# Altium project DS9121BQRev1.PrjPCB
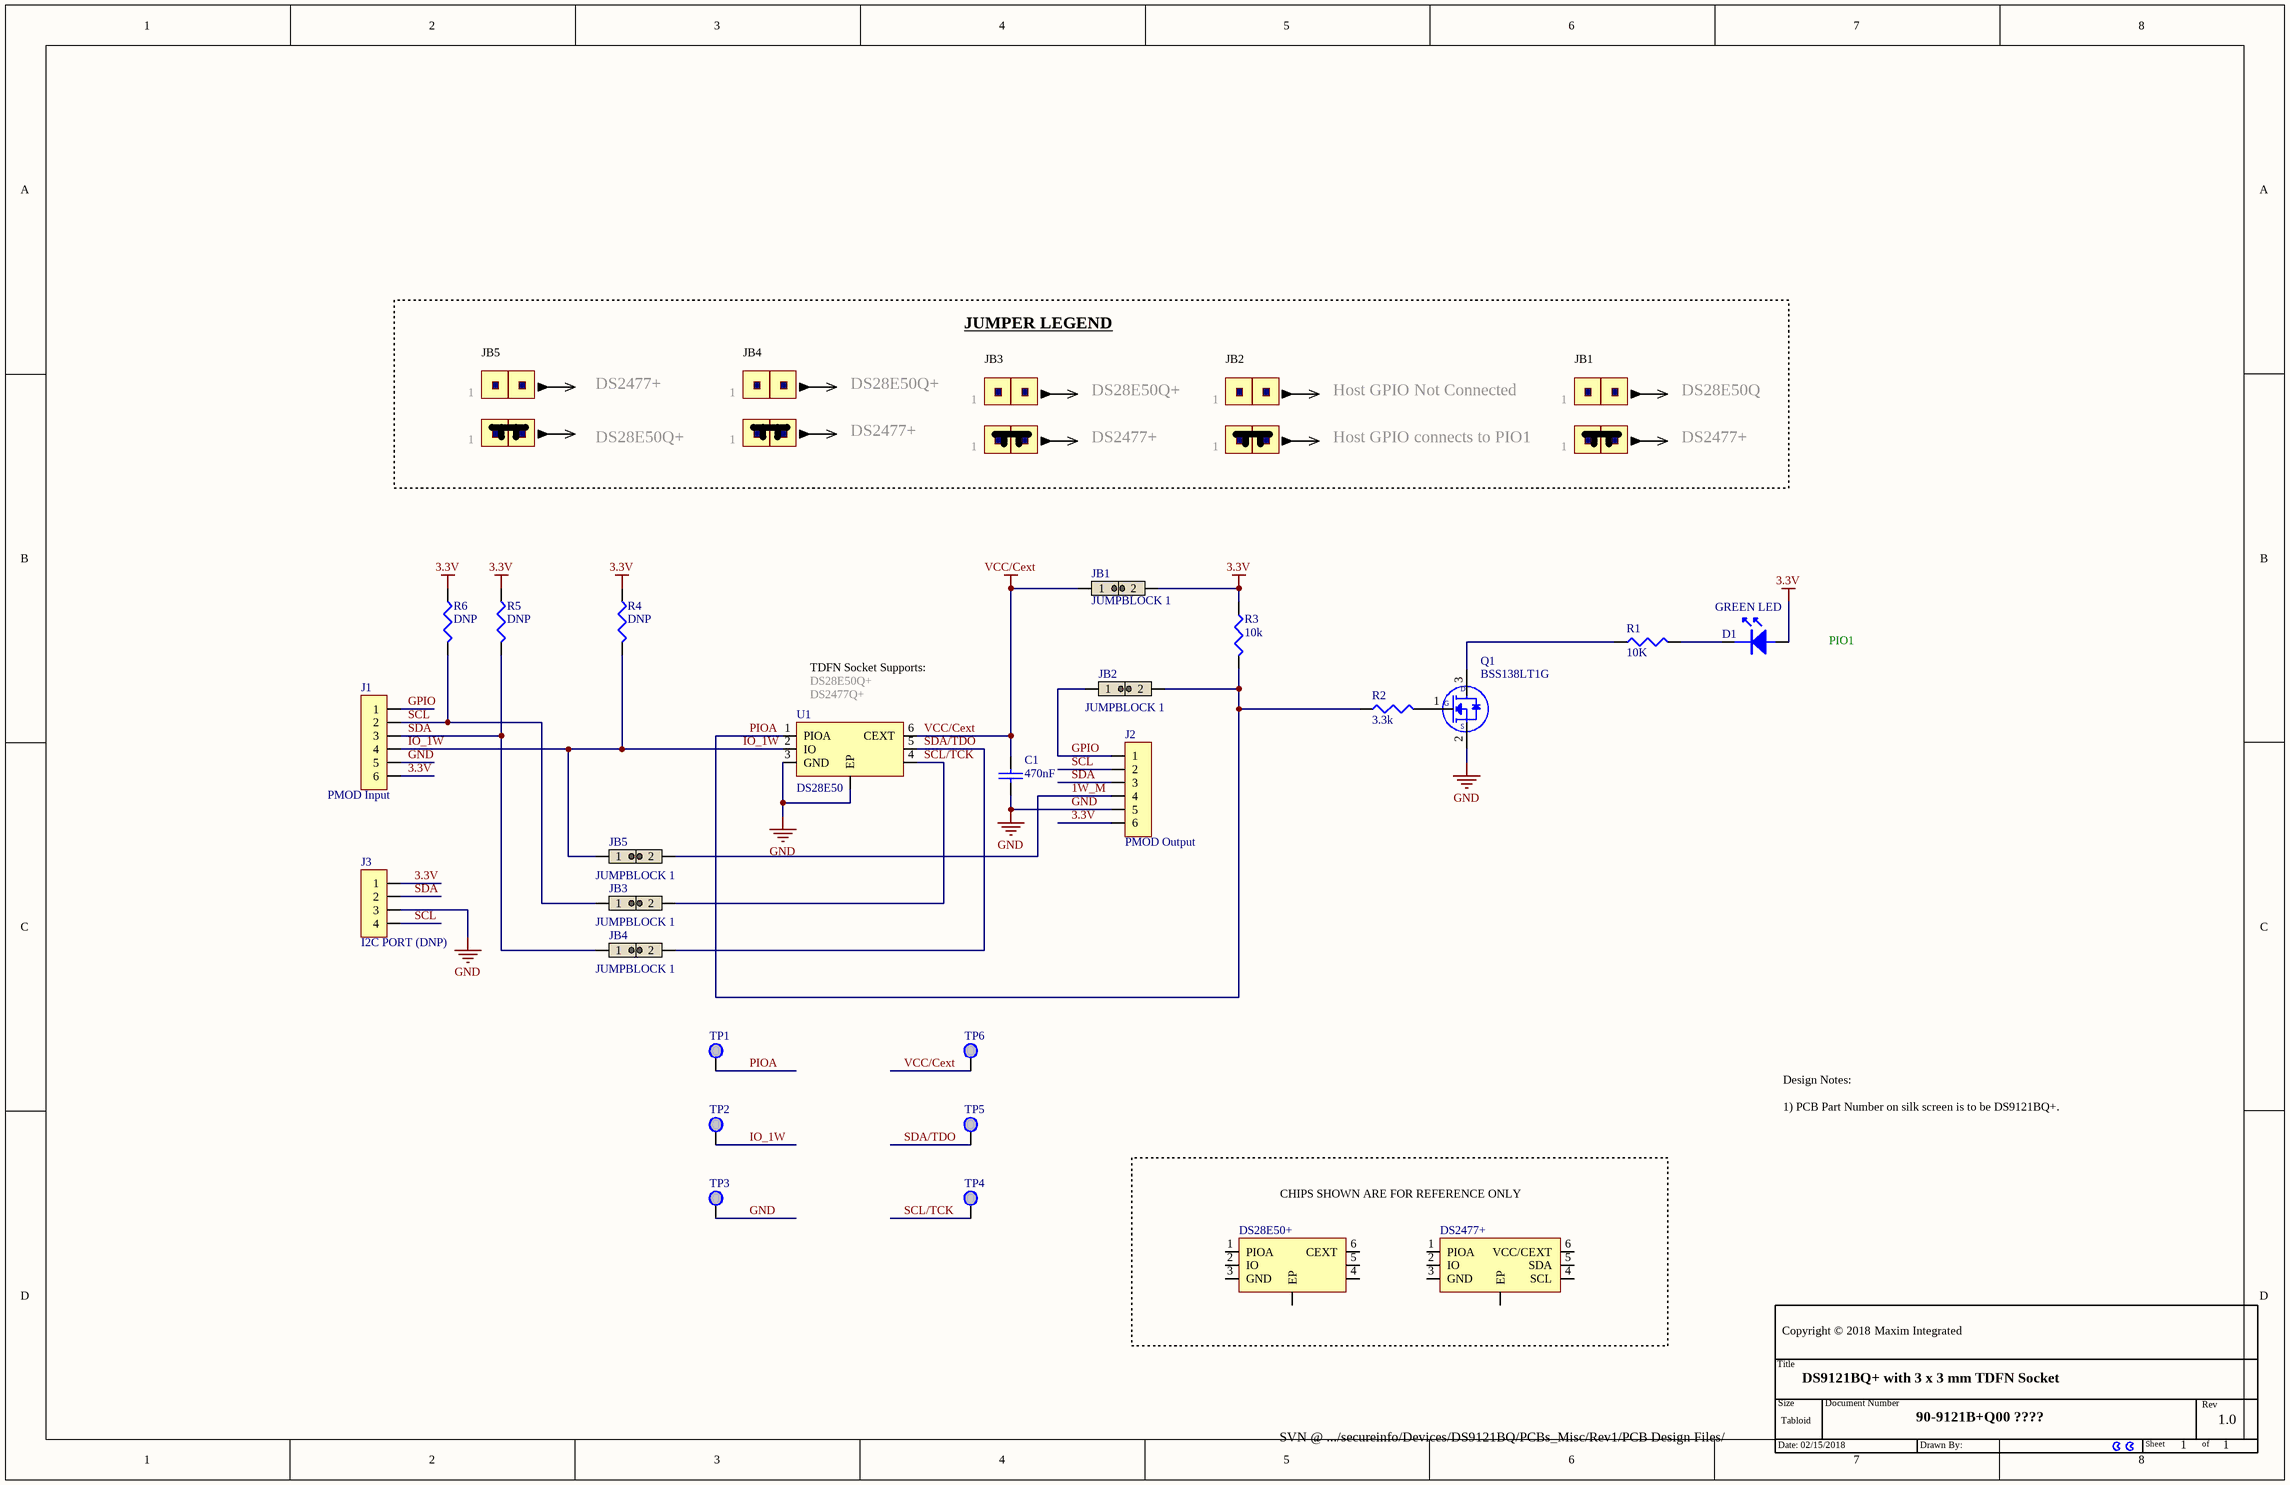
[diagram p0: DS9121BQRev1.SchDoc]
1 sheet, 29 parts. Net scope: global (net labels, ports and power ports of the same name join across sheets).
Board file: DS9121BQRev1.PcbDoc

## Sheet DS9121BQRev1.SchDoc
size Tabloid; PageSetup: Record=PageOptions|CenterHorizontal=True|CenterVertical=True|PrintScale=0.95|XCorrection=1.00|YCorrection=1.00|PrintKind=1|BorderSize=5000000|LeftOffset=0|BottomOffset=0|Orientation=2|PaperLength=4318|PaperWidth=2794|Scale=100|PaperSource=7|PrintQuality=600|MediaType=1|DitherType=10|PaperKind=11x17|PrintScaleMode=1

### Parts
*  Date: 02/15/2018  PG Count: 1  RevisonCode: 1.0  Copyright: 2018  TitleBlock: DS9121BQ+ with 3 x 3 mm TDFN Socket  Document Number: 90-9121B+Q00 ????  Size of Page: Tabloid  (hidden comment: AA_MAXIM title block w logo)  (graphical)
C1  470nF  [CAP0603-3D]
D1  GREEN LED  [0603LED-3DGREEN]
DS28E50+  (no value)  [TDFN3X2BURN]  (graphical)
DS2477+  DS2477  [TDFN3X2BURN]  (value not drawn)  (graphical)
J1  PMOD Input  [SIP6-SOCKET2-LA-3D]
J2  PMOD Output  [SIP6-HEADER-RA-LH-3D]
J3  I2C PORT (DNP)  [SIP4]
JB1  JUMPBLOCK 1  [SIP2-3D]
JB2  JUMPBLOCK 1  [SIP2-3D]
JB3  JUMPBLOCK 1  [SIP2-3D]
JB4  JUMPBLOCK 1  [SIP2-3D]
JB5  JUMPBLOCK 1  [SIP2SHUNT-3D]
Q1  BSS138LT1G  [16001-3D]
R1  10K  [0603-3D]
R2  3.3k  [0603-3D]
R3  10k  [0603-3D]
R4  DNP  [0603]
R5  DNP  [0603]
R6  DNP  [0603]
T1  PAC  [LOGOMAXNEWSMALL]  (value not drawn)  (no BOM)
T2  PAC  [PAC]  (value not drawn)  (no BOM)
TP1  TP  [TP-3D]  (value not drawn)  (no BOM)
TP2  TP  [TP-3D]  (value not drawn)  (no BOM)
TP3  TP  [TP-3D]  (value not drawn)  (no BOM)
TP4  TP  [TP-3D]  (value not drawn)  (no BOM)
TP5  TP  [TP-3D]  (value not drawn)  (no BOM)
TP6  TP  [TP-3D]  (value not drawn)  (no BOM)
U1  DS28E50  [TDFN6 3X2mm .95p BURN]

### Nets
3.3V: D1.2 J1.6 J2.6 J3.1 JB1.2 R3.2 R4.2 R5.2 R6.2
GND: C1.2 J1.5 J2.5 J3.3 Q1.2 TP3.1 U1.3(GND) U1.EP
VCC/Cext: C1.1 JB1.1 TP6.1 U1.6(CEXT)
1W_M: J2.4 JB5.2
GPIO: J1.1 J2.1 JB2.1
IO_1W: J1.4 JB5.1 R4.1 TP2.1 U1.2(IO)
PIOA: JB2.2 R2.2 R3.1 TP1.1 U1.1(PIOA)
SCL: J1.2 J2.2 J3.4 JB3.1 R6.1
SCL/TCK: JB3.2 TP4.1 U1.4
SDA: J1.3 J2.3 J3.2 JB4.1 R5.1
SDA/TDO: JB4.2 TP5.1 U1.5
NetD1_1: D1.1 R1.1
NetQ1_1: Q1.1 R2.1
NetQ1_3: Q1.3 R1.2

Not connected (* = marked no-connect by the designer): DS28E50+ 1(PIOA) 2(IO) 3(GND) 4 5 6(CEXT) EP; DS2477+ 1(PIOA) 2(IO) 3(GND) 4(SCL) 5(SDA) 6(VCC/CEXT) EP

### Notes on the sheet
- JB5
- JB4
- JUMPER LEGEND
- JB3
- JB2
- JB1
- 1
- DS2477+
- DS28E50Q+
- Host GPIO Not Connected
- DS28E50Q
- Host GPIO connects to PIO1
- (near U1) DS28E50Q+
- TDFN Socket Supports:
- (near U1) DS2477Q+
- (near D1) PIO1
- CHIPS SHOWN ARE FOR REFERENCE ONLY
  .
- (near *) Design Notes:
  1) PCB Part Number on silk screen is to be DS9121BQ+.
- SVN @ .../secureinfo/Devices/DS9121BQ/PCBs_Misc/Rev1/PCB Design Files/

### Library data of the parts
* = AA_MAXIM title block w logo: Place on Sheet and edit parameters to populate
C1 = CAP: Vendor: Digikey
D1 = LED: LED INGAN GREEN CLEAR 0603 SMD; Manufacture Name: Dialight; Part Number: 598-8081-107F; Internal Part Number: ED0950; Vendor Part Number: 350-2036-1-ND; Vendor: Digikey
DS28E50+ U1 = DS28E50: Manufacture Name: Maxim Integrated
DS2477+ = DS2477: DS2477+; Manufacture Name: Maxim Integrated
J1 = CON6: CONN RCPT .100" 6POS R/A SGL SN; Manufacture Name: Samtec Inc.; Part Number: SSW-106-02-T-S-RA
J2 = CON6: CONN HEADER FEMALE 6POS .1" GOLD; Manufacture Name: TE Connectivity; Part Number: 9-146285-0; Vendor Part Number: A32700-40-ND; Notes: Install on bottom of PCB; Vendor: Digikey
J3 = CON4: 4 Pin 100mil Female Connector; Manufacture Name: Samtec; Part Number: SSQ-104-02-T-S-RA; Internal Part Number: EH1244
Q1 = NCHAN FET: MOSFET N-CH 50V 200MA SOT-23; Manufacture Name: ON SEMICONDUCTOR; Internal Part Number: EQ0745; Notes: Vgs(th)(Max) 1.5V@1mA
R1 = RESISTOR: RES SMD 1K OHM 1% 1/10W 0603; Manufacture Name: Panasonic Electronic Components; Part Number: ERJ-3EKF1002V; Vendor Part Number: P10.0KHTR-ND; Vendor: Digikey
R2 = RESISTOR: RES 3.3K OHM 1/10W 1% 0603 SMD; Manufacture Name: Panasonic Electronic Components; Part Number: ERJ-3EKF3301V; Internal Part Number: ER0106033301; Vendor Part Number: P3.30KHTR-ND; Vendor: Digikey
R3-R6 = RESISTOR: RES SMD 10K OHM 1% 1/10W 0603; Manufacture Name: Panasonic Electronic Components; Part Number: ERJ-3EKF1002V; Vendor Part Number: P10.0KHTR-ND; Vendor: Digikey
TP1-TP6 = TP: Test Point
